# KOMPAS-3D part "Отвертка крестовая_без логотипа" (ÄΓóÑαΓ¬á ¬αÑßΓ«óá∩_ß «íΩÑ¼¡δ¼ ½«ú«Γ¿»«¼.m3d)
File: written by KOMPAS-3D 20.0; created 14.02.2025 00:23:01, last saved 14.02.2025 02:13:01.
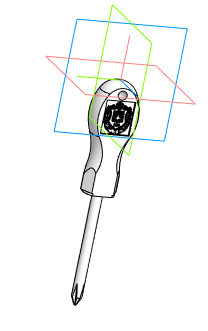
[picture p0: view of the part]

Document properties: Автор: User Windows; Полное имя файла: D:\Работа\ЦДП\2025 г\Отвертка крестовая_с логотипом МГТУ.m3d

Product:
- Part/product: Отвертка крестовая_без логотипа
    Материал: Полипропилен  ГОСТ 26996-86 (density 900 kg/m3)
    Масса: 0.00868856
  - Body: Тело 1
      Масса: 0.00871107

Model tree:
1. Операция без истории:1
2. Эскиз:1  (with: Операция без истории:1)
3. Элемент выдавливания:1
     Расстояние 1 = 1
4. Эскиз:2  (with: Элемент выдавливания:1)
5. Элемент выдавливания:4
     Расстояние 2 = 0.2
6. Эскиз:3  (with: Операция без истории:1)
7. Элемент выдавливания:5
     Расстояние 1 = 1
8. Эскиз:4  (with: Элемент выдавливания:1)
9. Элемент выдавливания:6  (labels: Полипропилен  ГОСТ 26996-86)
     Расстояние 2 = 0.5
